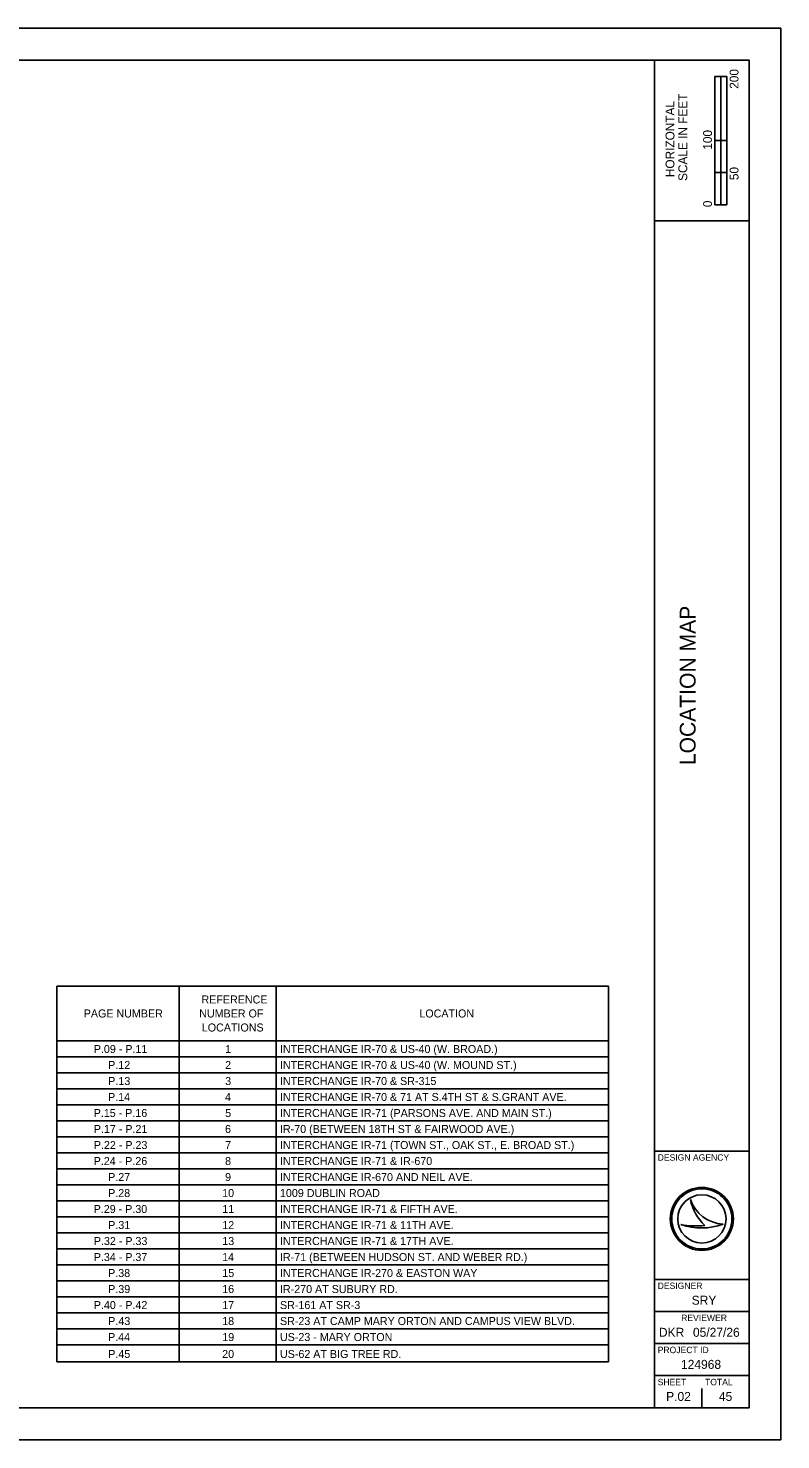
# Model space of a CAD drawing. Extents: x -1146 to -445, y -1283 to -822.
# Drawn here: x -690.7 to -445, y -1282.7 to -821.8 of the extents above; entities that cross this region are included whole.
import ezdxf

# ---------------------------------------------------------------- set-up
doc = ezdxf.new("R2010")
doc.units = 0
for name, color, linetype in [('Default', 7, 'Continuous'), ('SH_Border', 7, 'Continuous'), ('SH_Cut_Line', 7, 'Continuous'), ('SH_Data', 7, 'Continuous'), ('SH_Text', 7, 'Continuous')]:
    doc.layers.add(name, color=color, linetype=linetype)

msp = doc.modelspace()

# ---------------------------------------------------------------- linework, layer by layer
at = {"layer": 'Default'}
for points in [[(-681.37, -1134.58), (-641.41, -1134.58), (-641.41, -1134.58), (-681.37, -1134.58)], [(-681.37, -1134.58), (-649.71, -1134.58), (-649.71, -1134.58), (-681.37, -1134.58)], [(-681.37, -1134.58), (-572.87, -1134.58), (-572.87, -1134.58), (-681.37, -1134.58)]]:
    msp.add_lwpolyline(points, close=True, dxfattribs=at)
at = {"layer": 'SH_Border'}
for p, q in [((-486.25, -1272.23), (-486.25, -832.23)), ((-486.25, -884.61), (-455.34, -884.61)), ((-486.25, -1188.42), (-455.34, -1188.42)), ((-486.25, -1230.32), (-455.34, -1230.32)), ((-486.25, -1240.8), (-455.34, -1240.8)), ((-486.25, -1251.28), (-455.34, -1251.28)), ((-486.25, -1261.75), (-455.34, -1261.75))]:
    msp.add_line(p, q, dxfattribs=at)
msp.add_lwpolyline([(-1114.73, -832.23), (-455.34, -832.23), (-455.34, -1272.23), (-1114.73, -1272.23)], close=True, dxfattribs=at)
at = {"layer": 'SH_Cut_Line'}
msp.add_lwpolyline([(-1145.64, -1282.7), (-445.03, -1282.7), (-445.03, -821.75), (-1145.64, -821.75)], close=True, dxfattribs=at)
at = {"layer": 'SH_Data'}
for p, q in [((-466.53, -879.37), (-466.53, -837.47)), ((-462.67, -837.47), (-466.53, -837.47)), ((-466.53, -858.42), (-466.53, -837.47)), ((-466.53, -837.47), (-464.61, -837.47)), ((-464.61, -837.47), (-464.59, -837.47)), ((-464.59, -837.47), (-464.59, -858.42)), ((-462.67, -837.47), (-462.67, -879.37)), ((-464.59, -858.42), (-466.53, -858.42)), ((-462.69, -858.42), (-464.61, -858.42)), ((-464.61, -858.42), (-464.61, -868.9)), ((-462.69, -868.9), (-462.69, -858.42)), ((-464.61, -868.9), (-466.53, -868.9)), ((-466.53, -868.9), (-466.53, -879.37)), ((-464.61, -879.37), (-464.61, -868.9)), ((-464.61, -868.9), (-462.69, -868.9)), ((-462.67, -879.37), (-466.53, -879.37)), ((-466.53, -879.37), (-464.61, -879.37)), ((-681.37, -1134.58), (-501.25, -1134.58)), ((-681.37, -1134.58), (-681.37, -1257.23)), ((-641.41, -1134.58), (-641.41, -1257.23)), ((-609.75, -1134.58), (-609.75, -1257.23)), ((-501.25, -1134.58), (-501.25, -1257.23)), ((-681.37, -1152.41), (-501.25, -1152.41)), ((-681.37, -1157.64), (-501.25, -1157.64)), ((-681.37, -1162.86), (-501.25, -1162.86)), ((-681.37, -1168.09), (-501.25, -1168.09)), ((-681.37, -1173.31), (-501.25, -1173.31)), ((-681.37, -1178.54), (-501.25, -1178.54)), ((-681.37, -1183.76), (-501.25, -1183.76)), ((-681.37, -1188.99), (-501.25, -1188.99)), ((-681.37, -1194.22), (-501.25, -1194.22)), ((-681.37, -1199.44), (-501.25, -1199.44)), ((-681.37, -1204.67), (-501.25, -1204.67)), ((-474.55, -1204.2), (-474.55, -1204.2)), ((-681.37, -1209.89), (-501.25, -1209.89)), ((-470.79, -1209.37), (-470.79, -1209.37)), ((-463.84, -1212.26), (-463.84, -1212.26)), ((-681.37, -1215.12), (-501.25, -1215.12)), ((-477.65, -1212.45), (-477.65, -1212.45)), ((-681.37, -1220.34), (-501.25, -1220.34)), ((-681.37, -1225.57), (-501.25, -1225.57)), ((-681.37, -1230.79), (-501.25, -1230.79)), ((-681.37, -1236.02), (-501.25, -1236.02)), ((-681.37, -1241.24), (-501.25, -1241.24)), ((-681.37, -1246.47), (-501.25, -1246.47)), ((-681.37, -1251.7), (-501.25, -1251.7)), ((-681.37, -1257.23), (-501.25, -1257.23)), ((-470.79, -1272.23), (-470.79, -1265.94)), ((-478.52, -1268.56), (-478.52, -1268.56))]:
    msp.add_line(p, q, dxfattribs=at)
for radius in [10.3, 9.82, 9.82, 7.88]:
    msp.add_circle((-470.79, -1210.58), radius, dxfattribs=at)
for centre, radius, start, end in [((-463.25, -1200.33), 11.95, 198.9257, 198.9319), ((-458.49, -1200.9), 16.39, 191.6379, 191.6421), ((-463.25, -1200.33), 11.95, 198.9319, 267.1657), ((-458.49, -1200.9), 16.39, 191.6421, 226.0947), ((-471.01, -1192.66), 20.88, 251.4576, 290.0832), ((-472.89, -1186.8), 26.09, 259.4964, 259.4995), ((-471.01, -1192.66), 20.88, 251.4527, 251.4576), ((-472.89, -1186.8), 26.09, 259.4995, 276.6672)]:
    msp.add_arc(centre, radius, start, end, dxfattribs=at)

# ---------------------------------------------------------------- texts
for s, height, p in [('200', 2.885, (-458.83, -841.52)), ('SCALE IN FEET', 2.8848, (-475.58, -871.61)), ('HORIZONTAL', 2.885, (-479.75, -870.38)), ('100', 2.885, (-467.48, -861.42)), ('50', 2.885, (-458.83, -871.35)), ('0', 2.88, (-467.48, -880.18)), ('LOCATION MAP', 5.1515, (-472.85, -1062.4))]:
    msp.add_text(s, height=height, rotation=90, dxfattribs=at).set_placement(p)
for s, height, p in [('DESIGN AGENCY', 2.0952, (-485.22, -1191.56)), ('DESIGNER', 2.095, (-485.22, -1233.47)), ('SRY', 2.933, (-474.11, -1238.6)), ('REVIEWER', 2.095, (-477.55, -1243.94)), ('DKR', 2.933, (-484.82, -1249.08)), ('05/27/26', 2.933, (-473.7, -1249.08)), ('PROJECT ID', 2.095, (-485.22, -1254.42)), ('124968', 2.933, (-477.6, -1259.55)), ('SHEET', 2.095, (-485.22, -1264.9)), ('TOTAL', 2.095, (-469.76, -1264.9)), ('P.02', 2.933, (-482.44, -1270.03)), ('45', 2.933, (-465.23, -1270.03))]:
    msp.add_text(s, height=height, dxfattribs=at).set_placement(p)
at = {"layer": 'SH_Text'}
for s, height, p in [('REFERENCE ', 2.613, (-634.15, -1140.23)), ('PAGE NUMBER', 2.6127, (-672.58, -1144.8)), ('NUMBER OF ', 2.613, (-634.88, -1144.8)), ('LOCATION', 2.613, (-563.01, -1144.8)), ('LOCATIONS', 2.613, (-634.04, -1149.38)), ('P.09 - P.11', 2.6127, (-669.3, -1156.41)), ('1', 2.61, (-626.42, -1156.41)), ('INTERCHANGE IR-70 & US-40 (W. BROAD.)', 2.6127, (-608.52, -1156.41)), ('P.12', 2.613, (-664.59, -1161.63)), ('2', 2.61, (-626.42, -1161.63)), ('INTERCHANGE IR-70 & US-40 (W. MOUND ST.)', 2.6127, (-608.52, -1161.63)), ('P.13', 2.613, (-664.58, -1166.86)), ('3', 2.61, (-626.41, -1166.86)), ('INTERCHANGE IR-70 & SR-315', 2.6127, (-608.52, -1166.86)), ('P.14', 2.613, (-664.64, -1172.08)), ('4', 2.61, (-626.47, -1172.08)), ('INTERCHANGE IR-70 & 71 AT S.4TH ST & S.GRANT AVE.', 2.6127, (-608.52, -1172.08)), ('P.15 - P.16', 2.6127, (-669.33, -1177.31)), ('5', 2.61, (-626.41, -1177.31)), ('INTERCHANGE IR-71 (PARSONS AVE. AND MAIN ST.)', 2.6127, (-608.52, -1177.31)), ('P.17 - P.21', 2.6127, (-669.3, -1182.53)), ('6', 2.61, (-626.45, -1182.53)), ('IR-70 (BETWEEN 18TH ST & FAIRWOOD AVE.)', 2.6127, (-608.52, -1182.53)), ('P.22 - P.23', 2.6127, (-669.29, -1187.76)), ('7', 2.61, (-626.43, -1187.76)), ('INTERCHANGE IR-71 (TOWN ST., OAK ST., E. BROAD ST.)', 2.6127, (-608.52, -1187.76)), ('P.24 - P.26', 2.6127, (-669.33, -1192.99)), ('8', 2.61, (-626.44, -1192.99)), ('INTERCHANGE IR-71 & IR-670', 2.6127, (-608.52, -1192.99)), ('P.27', 2.613, (-664.61, -1198.21)), ('9', 2.61, (-626.43, -1198.21)), ('INTERCHANGE IR-670 AND NEIL AVE.', 2.6127, (-608.52, -1198.21)), ('P.28', 2.613, (-664.62, -1203.44)), ('10', 2.613, (-627.39, -1203.44)), ('1009 DUBLIN ROAD', 2.6127, (-608.52, -1203.44)), ('P.29 - P.30', 2.6127, (-669.34, -1208.66)), ('11', 2.613, (-627.36, -1208.66)), ('INTERCHANGE IR-71 & FIFTH AVE.', 2.6127, (-608.52, -1208.66)), ('P.31', 2.613, (-664.59, -1213.89)), ('12', 2.613, (-627.36, -1213.89)), ('INTERCHANGE IR-71 & 11TH AVE.', 2.6127, (-608.52, -1213.89)), ('P.32 - P.33', 2.6127, (-669.29, -1219.11)), ('13', 2.613, (-627.35, -1219.11)), ('INTERCHANGE IR-71 & 17TH AVE.', 2.6127, (-608.52, -1219.11)), ('P.34 - P.37', 2.6127, (-669.31, -1224.34)), ('14', 2.613, (-627.4, -1224.34)), ('IR-71 (BETWEEN HUDSON ST. AND WEBER RD.)', 2.6127, (-608.52, -1224.34)), ('P.38', 2.613, (-664.62, -1229.56)), ('15', 2.613, (-627.35, -1229.56)), ('INTERCHANGE IR-270 & EASTON WAY', 2.6127, (-608.52, -1229.56)), ('P.39', 2.613, (-664.6, -1234.79)), ('16', 2.613, (-627.38, -1234.79)), ('IR-270 AT SUBURY RD.', 2.6127, (-608.52, -1234.79)), ('P.40 - P.42', 2.6127, (-669.3, -1240.02)), ('17', 2.613, (-627.37, -1240.02)), ('SR-161 AT SR-3', 2.6127, (-608.52, -1240.02)), ('P.43', 2.613, (-664.58, -1245.24)), ('18', 2.613, (-627.38, -1245.24)), ('SR-23 AT CAMP MARY ORTON AND CAMPUS VIEW BLVD.', 2.6127, (-608.52, -1245.24)), ('P.44', 2.613, (-664.64, -1250.47)), ('19', 2.613, (-627.36, -1250.47)), ('US-23 - MARY ORTON', 2.6127, (-608.52, -1250.47)), ('P.45', 2.613, (-664.58, -1256)), ('20', 2.613, (-627.39, -1256)), ('US-62 AT BIG TREE RD.', 2.6127, (-608.52, -1256))]:
    msp.add_text(s, height=height, dxfattribs=at).set_placement(p)

doc.saveas('drawing.dxf')
